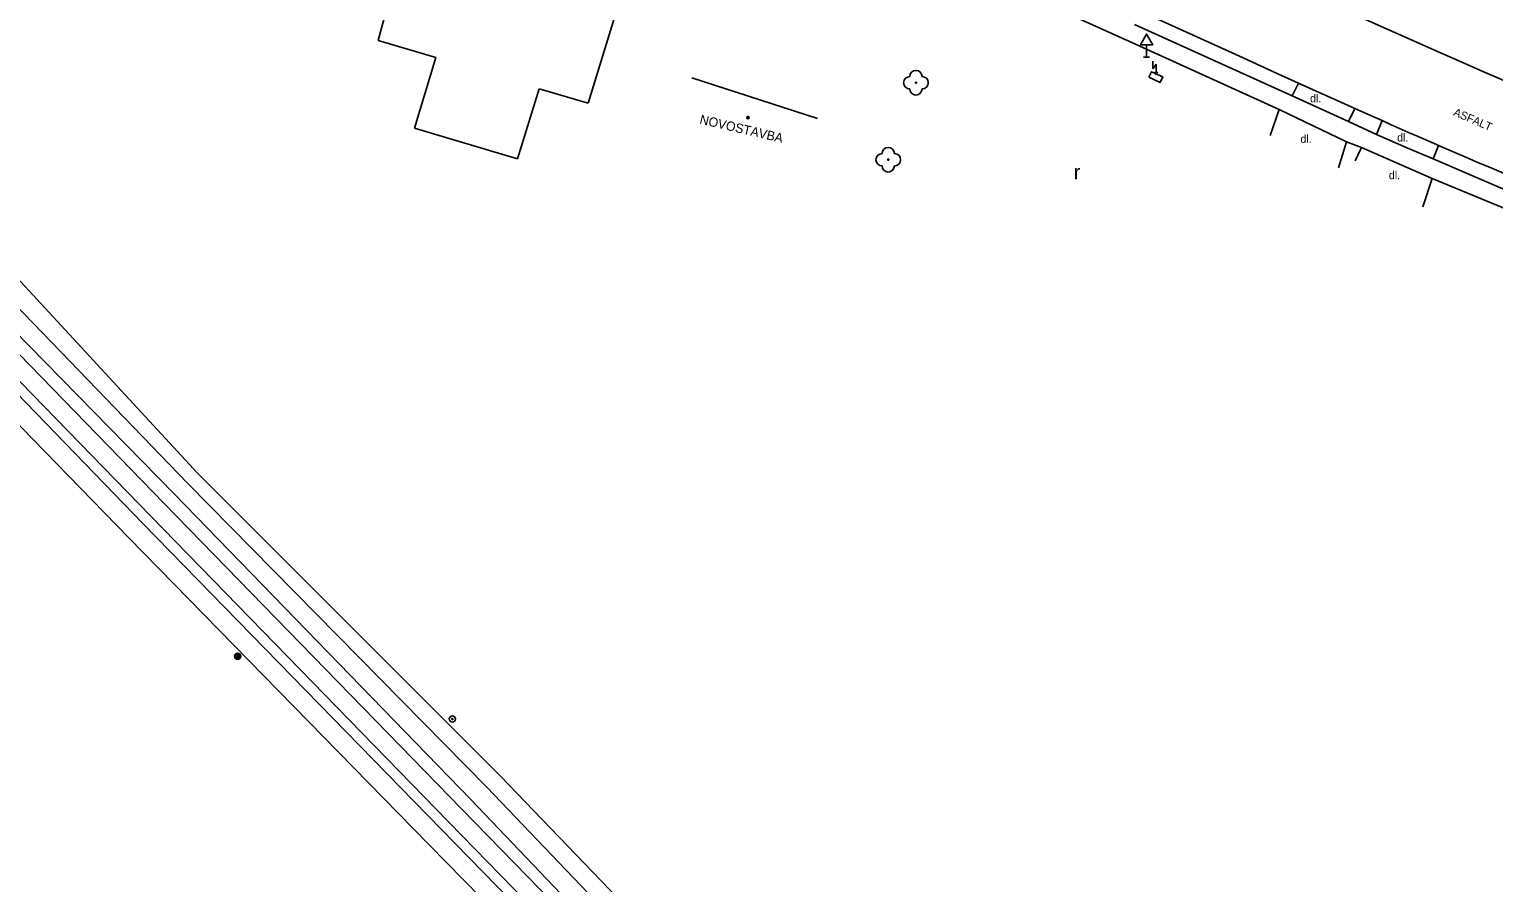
# Model space of a CAD drawing. Extents: x -540235 to -537963, y -1184915 to -1183660.
# Drawn here: x -538238.6 to -538119.7, y -1184015.5 to -1183946.2 of the extents above; entities that cross this region are included whole.
import ezdxf

# ---------------------------------------------------------------- set-up
doc = ezdxf.new("R2010")
doc.units = 0
for name, color, linetype in [('Vrstva 10', 7, 'Continuous'), ('Vrstva 11', 7, 'Continuous'), ('Vrstva 12', 7, 'Continuous'), ('Vrstva 14', 7, 'Continuous'), ('Vrstva 22', 7, 'Continuous'), ('Vrstva 24', 7, 'Continuous'), ('Vrstva 25', 7, 'Continuous'), ('Vrstva 34', 7, 'Continuous'), ('Vrstva 36', 7, 'Continuous'), ('Vrstva 39', 7, 'Continuous'), ('Vrstva 40', 7, 'Continuous'), ('Vrstva 41', 7, 'Continuous'), ('Vrstva 5', 7, 'Continuous')]:
    doc.layers.add(name, color=color, linetype=linetype)

msp = doc.modelspace()

# ---------------------------------------------------------------- linework, layer by layer
at = {"layer": 'Vrstva 10'}
for points in [[(-538154.069, -1183942.171), (-538152.987, -1183942.664), (-538148.42, -1183944.742), (-538140.365, -1183948.408)], [(-538121.87, -1183949.08), (-538124.524, -1183947.908), (-538127.009, -1183946.805), (-538129.338, -1183945.767), (-538130.183, -1183945.389)], [(-538140.365, -1183948.408), (-538136.937, -1183949.962), (-538135.561, -1183950.584), (-538134.364, -1183951.124), (-538132.432, -1183951.992)], [(-538112.781, -1183952.939), (-538113.923, -1183952.469), (-538114.92, -1183952.054), (-538115.792, -1183951.69), (-538116.856, -1183951.241), (-538117.316, -1183951.047), (-538118.457, -1183950.561), (-538119.311, -1183950.194), (-538120.592, -1183949.64), (-538121.87, -1183949.08)], [(-538132.432, -1183951.992), (-538130.996, -1183952.635), (-538129.533, -1183953.29), (-538128.77, -1183953.63), (-538128.082, -1183953.936), (-538126.63, -1183954.58), (-538125.842, -1183954.928), (-538124.362, -1183955.575)], [(-538124.362, -1183955.575), (-538124.177, -1183955.655), (-538123.065, -1183956.135), (-538121.928, -1183956.622), (-538120.933, -1183957.045)], [(-538120.933, -1183957.045), (-538120.06, -1183957.413), (-538118.532, -1183958.053), (-538117.635, -1183958.425), (-538117.384, -1183958.529), (-538116.266, -1183958.988), (-538115.659, -1183959.237), (-538113.93, -1183959.94), (-538112.464, -1183960.529)]]:
    msp.add_lwpolyline(points, dxfattribs=at)
at = {"layer": 'Vrstva 11'}
for p, q in [((-538149.34, -1183947.19), (-538154.39, -1183944.92)), ((-538136.08, -1183951.61), (-538148.87, -1183945.83)), ((-538137.13, -1183952.74), (-538149.34, -1183947.19)), ((-538136.08, -1183951.61), (-538135.561, -1183950.584)), ((-538131.49, -1183953.7), (-538136.08, -1183951.61)), ((-538137.13, -1183952.74), (-538137.87, -1183954.85)), ((-538131.67, -1183955.36), (-538137.13, -1183952.74)), ((-538130.996, -1183952.635), (-538131.49, -1183953.7)), ((-538131.49, -1183953.7), (-538129.22, -1183954.75)), ((-538129.22, -1183954.75), (-538128.77, -1183953.63)), ((-538132.3, -1183957.47), (-538131.67, -1183955.36)), ((-538131.67, -1183955.36), (-538130.43, -1183955.8)), ((-538130.43, -1183955.8), (-538130.97, -1183956.9)), ((-538124.69, -1183958.34), (-538130.43, -1183955.8)), ((-538124.177, -1183955.655), (-538124.61, -1183956.73)), ((-538124.61, -1183956.73), (-538118.14, -1183959.51)), ((-538124.69, -1183958.34), (-538125.47, -1183960.63)), ((-538114.31, -1183962.64), (-538124.69, -1183958.34))]:
    msp.add_line(p, q, dxfattribs=at)
msp.add_lwpolyline([(-538124.61, -1183956.73), (-538126.82, -1183955.81), (-538129.22, -1183954.75)], dxfattribs=at)
at = {"layer": 'Vrstva 12'}
for p, q in [((-538253.91, -1183957.76), (-538227.69, -1183984.7)), ((-538254.99, -1183958.81), (-538228.77, -1183985.73)), ((-538227.69, -1183984.7), (-538203.48, -1184009.53)), ((-538228.77, -1183985.73), (-538204.56, -1184010.56)), ((-538203.48, -1184009.53), (-538180.44, -1184033.19)), ((-538204.56, -1184010.56), (-538181.51, -1184034.24))]:
    msp.add_line(p, q, dxfattribs=at)
at = {"layer": 'Vrstva 14'}
for p, q in [((-538250.65, -1183954.48), (-538224.97, -1183982.24)), ((-538252.11, -1183955.81), (-538225.77, -1183983.08)), ((-538253.23, -1183957.04), (-538226.86, -1183983.95)), ((-538229.39, -1183986.35), (-538255.63, -1183959.29)), ((-538230.59, -1183987.46), (-538256.89, -1183960.49)), ((-538224.97, -1183982.24), (-538200.4, -1184006.8)), ((-538225.77, -1183983.08), (-538201.49, -1184007.73)), ((-538226.86, -1183983.95), (-538202.77, -1184008.73)), ((-538205.19, -1184011.13), (-538229.39, -1183986.35)), ((-538206.18, -1184012.39), (-538230.59, -1183987.46)), ((-538200.4, -1184006.8), (-538177.36, -1184030.72)), ((-538201.49, -1184007.73), (-538178.51, -1184031.72)), ((-538202.77, -1184008.73), (-538179.81, -1184032.74)), ((-538182.11, -1184034.75), (-538205.19, -1184011.13)), ((-538183.36, -1184035.55), (-538206.18, -1184012.39))]:
    msp.add_line(p, q, dxfattribs=at)
at = {"layer": 'Vrstva 22'}
for centre in [(-538166.63, -1183950.55), (-538168.88, -1183956.8)]:
    msp.add_circle(centre, 0.05, dxfattribs=at)
for centre, start, end in [((-538167.13, -1183950.55), 90, 270), ((-538166.63, -1183950.05), 0, 180), ((-538166.13, -1183950.55), 270, 90), ((-538166.63, -1183951.05), 180, 0), ((-538168.88, -1183956.3), 0, 180), ((-538169.38, -1183956.8), 90, 270), ((-538168.88, -1183957.3), 180, 0), ((-538168.38, -1183956.8), 270, 90)]:
    msp.add_arc(centre, 0.5, start, end, dxfattribs=at)
at = {"layer": 'Vrstva 24'}
for p, q in [((-538147.38, -1183948.794), (-538147.38, -1183949.421)), ((-538147.38, -1183949.421), (-538147.13, -1183949.045)), ((-538147.13, -1183949.045), (-538147.13, -1183949.92)), ((-538147.239, -1183949.675), (-538147.13, -1183949.92)), ((-538147.13, -1183949.92), (-538147.019, -1183949.675))]:
    msp.add_line(p, q, dxfattribs=at)
msp.add_lwpolyline([(-538147.709, -1183950.112), (-538146.797, -1183950.524), (-538146.591, -1183950.068), (-538147.503, -1183949.656)], close=True, dxfattribs=at)
at = {"layer": 'Vrstva 25'}
for centre, radius in [((-538221.72, -1183997.1), 0.25), ((-538221.72, -1183997.1), 0.2), ((-538221.72, -1183997.1), 0.15), ((-538221.72, -1183997.1), 0.1), ((-538221.72, -1183997.1), 0.05), ((-538204.28, -1184002.19), 0.25), ((-538204.28, -1184002.19), 0.05)]:
    msp.add_circle(centre, radius, dxfattribs=at)
at = {"layer": 'Vrstva 34'}
for p, q in [((-538147.9, -1183947.474), (-538147.9, -1183948.49)), ((-538148.15, -1183948.49), (-538147.65, -1183948.49))]:
    msp.add_line(p, q, dxfattribs=at)
msp.add_lwpolyline([(-538148.4, -1183947.474), (-538147.4, -1183947.474), (-538147.9, -1183946.606)], close=True, dxfattribs=at)
at = {"layer": 'Vrstva 39'}
for radius in [0.09, 0.0398]:
    msp.add_circle((-538180.275, -1183953.385), radius, dxfattribs=at)
at = {"layer": 'Vrstva 5'}
for p, q in [((-538207.53, -1183936.76), (-538210.32, -1183947.12)), ((-538193.24, -1183952.22), (-538190.11, -1183941.95)), ((-538210.32, -1183947.12), (-538205.63, -1183948.5)), ((-538205.63, -1183948.5), (-538207.37, -1183954.25)), ((-538174.62, -1183953.46), (-538184.83, -1183950.16)), ((-538198.98, -1183956.74), (-538197.22, -1183951.05)), ((-538197.22, -1183951.05), (-538193.24, -1183952.22)), ((-538207.37, -1183954.25), (-538198.98, -1183956.74))]:
    msp.add_line(p, q, dxfattribs=at)

# ---------------------------------------------------------------- texts
at = {"layer": 'Vrstva 36'}
msp.add_text('r', height=1.2, dxfattribs=at).set_placement((-538153.813, -1183958.407))
at = {"layer": 'Vrstva 40'}
for p in [(-538134.622, -1183952.147), (-538135.401, -1183955.427), (-538127.548, -1183955.324), (-538128.223, -1183958.384)]:
    msp.add_text('dl.', height=0.65, dxfattribs=at).set_placement(p)
msp.add_text('ASFALT', height=0.65, rotation=336.723889, dxfattribs=at).set_placement((-538123.035, -1183953.178))
at = {"layer": 'Vrstva 41'}
msp.add_text('NOVOSTAVBA', height=0.75, rotation=346.828986, dxfattribs=at).set_placement((-538184.247, -1183953.863))

doc.saveas('drawing.dxf')
